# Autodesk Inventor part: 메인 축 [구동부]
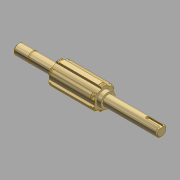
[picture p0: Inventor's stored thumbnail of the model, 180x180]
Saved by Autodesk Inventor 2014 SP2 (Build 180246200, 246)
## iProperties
Created: 2015-11
Part Number: 메인 축 [구동부]
Document SubType Name: 모델링
Designer: mdu
Mass: 21.4461 g
Surface Area: 72.5104 cm^2
Volume: 21.4461 cm^3
Density: 1 g/cm^3
Material: 일반
Appearance: 기본값
변환 표준: STEP AP214IS
파일 이름: C:\Users\SeoGD\Desktop\?쒗뿕\硫붿씤 異?.stp
전처리기: Build: 253, Release: 2010 SP1 - Date: Wed 07/29/2009
전송 단위: 밀리미터
불확실성: 0.01
Author: mdu
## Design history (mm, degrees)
sketch "스케치1"
  geometry: L1 (-69.5, 0)-(69.5, 0); L2 (69.5, 0)-(69.5, 5); L3 (69.5, 5)-(55.5, 5); L4 (55.5, 5)-(55.5, 4.8); L5 (55.5, 4.8)-(54.35, 4.8); L6 (54.35, 4.8)-(54.35, 5); L7 (54.35, 5)-(30.5, 5); L8 (30.5, 5)-(30.5, 9); L9 (30.5, 9)-(-13.5, 9); L10 (-13.5, 9)-(-13.5, 7); L11 (-13.5, 7)-(-17.5, 7); L12 (-17.5, 7)-(-17.5, 5); L13 (-17.5, 5)-(-69.5, 5); L14 (-69.5, 5)-(-69.5, 0); 2 further points
  constraints: 28 end point, 9 parallel, 4 collinear, 2 perpendicular, 1 coincident, 1 horizontal, 1 midpoint
  dimensions: "d2" = 1.15 distance between parallel lines of L6 L4; "d3" = 10 diameter of L3 L1; "d4" = 9.6 diameter of L5 L1; "d6" = 44 distance between parallel lines of L10 L8; "d7" = 4 distance between parallel lines of L12 L10; "d8" = 14 diameter of L11 L1; "d9" = 18 diameter of L9 L1; "d33" = 52 distance from line of L12.end L14; "d37" = 39 distance between parallel lines of L8 L2; "d38" = 14 distance between parallel lines of L2 L4
revolve "회전1" sketch "스케치1" stored, may be unused: angle "d10" = 90 deg
sketch "스케치2"
  geometry: L1 (2.5, 10.712)-(2.5, 8.646); L2 (-2.5, 10.712)-(-2.5, 8.646); A1 r 9 centre (0, 0) between (2.5, 8.646) and (-2.5, 8.646) reference; A2 r 11 centre (0, 0) between (2.5, 10.712) and (-2.5, 10.712); 1 further point
  constraints: 4 end point, 4 point on circle, 2 parallel, 1 centre point, 1 coincident, 1 vertical
  dimensions: "d11" = 22 diameter of A2; "d12" = 5 distance between parallel lines of L1 L2
extrude "돌출1" join sketch "스케치2" stored distance "d13" = 10; taper "d14" = 0 deg
chamfer "모따기1" distance "d15" = 1; stored, may be unused: second distance "d16" = 2, angle "d17" = 45 deg
node "작업 평면1"
node "작업 평면2"
sketch "스케치3"
  geometry: L1 (2.5, 10.712)-(2.5, 10.198); L2 (-2.5, 10.712)-(-2.5, 10.198); A1 r 11 centre (0, 0) between (2.5, 10.712) and (-2.5, 10.712) reference; A2 r 10.5 centre (0, 0) between (2.5, 10.198) and (-2.5, 10.198); 1 further point
  constraints: 4 end point, 2 point on circle, 1 centre point, 1 coincident, 1 parallel, 1 vertical
  dimensions: "d19" = 21 diameter of A2
extrude "돌출2" cut sketch "스케치3" distance "d20" = 1.35; taper "d21" = 0 deg
node "작업 평면3"
sketch "스케치4"
  geometry: L1 (-26, -5)-(-26, 5) reference; L2 (-26, 1.5)-(-12.5, 1.5); L3 (-12.5, -1.5)-(-26, -1.5); A1 r 1.5 centre (-12.5, 0) between (-12.5, -1.5) and (-12.5, 1.5); 2 further points
  constraints: 4 end point, 2 perpendicular, 2 point on circle, 2 point on line, 2 tangent, 1 centre point, 1 horizontal alignment, 1 midpoint
  dimensions: "d25" = 3 distance between parallel lines of L3 L2; "d26" = 15 dimension on A1 L1
extrude "돌출3" cut sketch "스케치4" distance "d27" = 1.8; taper "d28" = 0 deg
chamfer "모따기2" distance "d29" = 1; stored, may be unused: second distance "d30" = 2, angle "d31" = 45 deg
node "솔리드1"
node "솔리드 본체"
node "곡면 본체"
mirror "대칭1"
pattern_circular "원형 패턴1" dims "d23" = 360 deg
node "솔리드2"
other parameters: "d18" = -1.65
